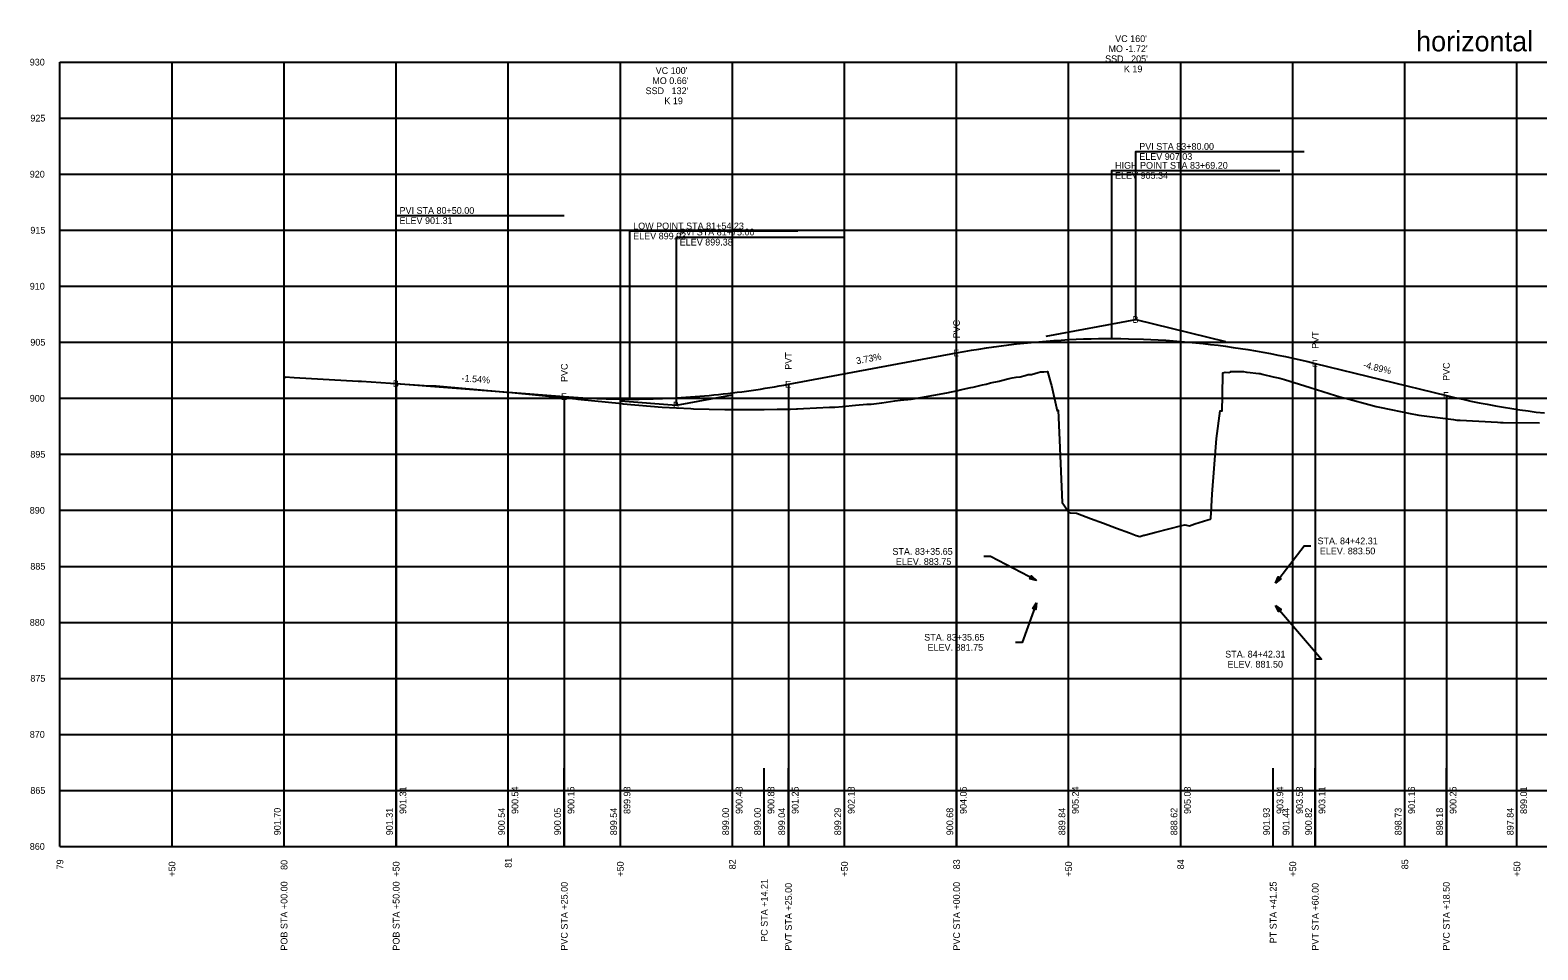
# Model space of a CAD drawing. Extents: x 76292 to 78417, y 50412 to 52585.
# Drawn here: x 76292 to 76965, y 52134 to 52544 of the extents above; entities that cross this region are included whole.
import ezdxf

# ---------------------------------------------------------------- set-up
doc = ezdxf.new("R2010")
doc.units = 0
for name, color, linetype in [('1', 7, 'Continuous'), ('2', 7, 'Continuous'), ('3', 7, 'Continuous'), ('32', 7, 'Continuous'), ('33', 7, 'Continuous'), ('63', 7, 'Continuous'), ('Default', 7, 'Continuous')]:
    doc.layers.add(name, color=color, linetype=linetype)

msp = doc.modelspace()

# ---------------------------------------------------------------- linework, layer by layer
at = {"layer": '1'}
for p, q in [((76305.34, 52180.05), (77605.34, 52180.05)), ((76305.34, 52180.05), (76305.34, 52180.05)), ((76355.34, 52180.05), (76355.34, 52180.05)), ((76405.34, 52180.05), (76405.34, 52180.05)), ((76455.34, 52180.05), (76455.34, 52180.05)), ((76505.34, 52180.05), (76505.34, 52180.05)), ((76555.34, 52180.05), (76555.34, 52180.05)), ((76605.34, 52180.05), (76605.34, 52180.05)), ((76655.34, 52180.05), (76655.34, 52180.05)), ((76705.34, 52180.05), (76705.34, 52180.05)), ((76755.34, 52180.05), (76755.34, 52180.05)), ((76805.34, 52180.05), (76805.34, 52180.05)), ((76855.34, 52180.05), (76855.34, 52180.05)), ((76905.34, 52180.05), (76905.34, 52180.05)), ((76955.34, 52180.05), (76955.34, 52180.05))]:
    msp.add_line(p, q, dxfattribs=at)
for points in [[(76785.34, 52415.2), (76785.34, 52490.2), (76860.34, 52490.2)], [(76774.54, 52406.73), (76774.54, 52481.73), (76849.54, 52481.73)], [(76455.34, 52386.6), (76455.34, 52461.6), (76530.34, 52461.6)], [(76559.57, 52379.7), (76559.57, 52454.7), (76634.57, 52454.7)], [(76580.34, 52376.97), (76580.34, 52451.97), (76655.34, 52451.97)], [(76705.34, 52400.28), (76705.34, 52180.05), (76705.34, 52180.05), (76705.34, 52180.05)], [(76865.34, 52395.62), (76865.34, 52180.05), (76865.34, 52180.05), (76865.34, 52180.05)], [(76455.34, 52386.6), (76455.34, 52180.05), (76455.34, 52180.05), (76455.34, 52180.05)], [(76630.34, 52386.29), (76630.34, 52180.05), (76630.34, 52180.05), (76630.34, 52180.05)], [(76530.34, 52380.82), (76530.34, 52180.05), (76530.34, 52180.05), (76530.34, 52180.05)], [(76923.84, 52381.31), (76923.84, 52180.05), (76923.84, 52180.05), (76923.84, 52180.05)], [(76305.34, 52180.05), (76305.34, 52215.05)], [(76305.34, 52180.05), (76305.34, 52215.05)], [(76305.34, 52180.05), (76305.34, 52215.05)], [(76305.34, 52180.05), (76305.34, 52215.05)], [(76355.34, 52180.05), (76355.34, 52215.05)], [(76355.34, 52180.05), (76355.34, 52215.05)], [(76355.34, 52180.05), (76355.34, 52215.05)], [(76355.34, 52180.05), (76355.34, 52215.05)], [(76405.34, 52180.05), (76405.34, 52215.05)], [(76405.34, 52180.05), (76405.34, 52215.05)], [(76405.34, 52180.05), (76405.34, 52215.05)], [(76405.34, 52180.05), (76405.34, 52215.05)], [(76455.34, 52180.05), (76455.34, 52215.05)], [(76455.34, 52180.05), (76455.34, 52215.05)], [(76455.34, 52180.05), (76455.34, 52215.05)], [(76455.34, 52180.05), (76455.34, 52215.05)], [(76505.34, 52180.05), (76505.34, 52215.05)], [(76505.34, 52180.05), (76505.34, 52215.05)], [(76505.34, 52180.05), (76505.34, 52215.05)], [(76505.34, 52180.05), (76505.34, 52215.05)], [(76530.34, 52180.05), (76530.34, 52215.05)], [(76530.34, 52180.05), (76530.34, 52215.05)], [(76530.34, 52180.05), (76530.34, 52215.05)], [(76530.34, 52180.05), (76530.34, 52215.05)], [(76555.34, 52180.05), (76555.34, 52215.05)], [(76555.34, 52180.05), (76555.34, 52215.05)], [(76555.34, 52180.05), (76555.34, 52215.05)], [(76555.34, 52180.05), (76555.34, 52215.05)], [(76605.34, 52180.05), (76605.34, 52215.05)], [(76605.34, 52180.05), (76605.34, 52215.05)], [(76605.34, 52180.05), (76605.34, 52215.05)], [(76605.34, 52180.05), (76605.34, 52215.05)], [(76619.55, 52180.05), (76619.55, 52215.05)], [(76619.55, 52180.05), (76619.55, 52215.05)], [(76619.55, 52180.05), (76619.55, 52215.05)], [(76619.55, 52180.05), (76619.55, 52215.05)], [(76630.34, 52180.05), (76630.34, 52215.05)], [(76630.34, 52180.05), (76630.34, 52215.05)], [(76630.34, 52180.05), (76630.34, 52215.05)], [(76630.34, 52180.05), (76630.34, 52215.05)], [(76655.34, 52180.05), (76655.34, 52215.05)], [(76655.34, 52180.05), (76655.34, 52215.05)], [(76655.34, 52180.05), (76655.34, 52215.05)], [(76655.34, 52180.05), (76655.34, 52215.05)], [(76705.34, 52180.05), (76705.34, 52215.05)], [(76705.34, 52180.05), (76705.34, 52215.05)], [(76705.34, 52180.05), (76705.34, 52215.05)], [(76705.34, 52180.05), (76705.34, 52215.05)], [(76755.34, 52180.05), (76755.34, 52215.05)], [(76755.34, 52180.05), (76755.34, 52215.05)], [(76755.34, 52180.05), (76755.34, 52215.05)], [(76755.34, 52180.05), (76755.34, 52215.05)], [(76805.34, 52180.05), (76805.34, 52215.05)], [(76805.34, 52180.05), (76805.34, 52215.05)], [(76805.34, 52180.05), (76805.34, 52215.05)], [(76805.34, 52180.05), (76805.34, 52215.05)], [(76846.59, 52180.05), (76846.59, 52215.05)], [(76846.59, 52180.05), (76846.59, 52215.05)], [(76846.59, 52180.05), (76846.59, 52215.05)], [(76846.59, 52180.05), (76846.59, 52215.05)], [(76855.34, 52180.05), (76855.34, 52215.05)], [(76855.34, 52180.05), (76855.34, 52215.05)], [(76855.34, 52180.05), (76855.34, 52215.05)], [(76855.34, 52180.05), (76855.34, 52215.05)], [(76865.34, 52180.05), (76865.34, 52215.05)], [(76865.34, 52180.05), (76865.34, 52215.05)], [(76865.34, 52180.05), (76865.34, 52215.05)], [(76865.34, 52180.05), (76865.34, 52215.05)], [(76905.34, 52180.05), (76905.34, 52215.05)], [(76905.34, 52180.05), (76905.34, 52215.05)], [(76905.34, 52180.05), (76905.34, 52215.05)], [(76905.34, 52180.05), (76905.34, 52215.05)], [(76923.84, 52180.05), (76923.84, 52215.05)], [(76923.84, 52180.05), (76923.84, 52215.05)], [(76923.84, 52180.05), (76923.84, 52215.05)], [(76923.84, 52180.05), (76923.84, 52215.05)], [(76955.34, 52180.05), (76955.34, 52215.05)], [(76955.34, 52180.05), (76955.34, 52215.05)], [(76955.34, 52180.05), (76955.34, 52215.05)], [(76955.34, 52180.05), (76955.34, 52215.05)]]:
    msp.add_lwpolyline(points, dxfattribs=at)
at = {"layer": '2'}
msp.add_lwpolyline([(76405.34, 52388.53), (76405.72, 52389.55), (76405.74, 52389.55), (76405.77, 52389.55), (76405.8, 52389.55), (76405.83, 52389.55), (76405.84, 52389.55), (76409.89, 52389.33), (76438.41, 52387.74), (76438.7, 52387.72), (76439, 52387.7), (76439.5, 52387.68), (76439.8, 52387.66), (76469.99, 52385.61), (76470.25, 52385.62), (76473.18, 52385.54), (76504.5, 52382.84), (76504.62, 52382.82), (76504.68, 52382.82), (76505.52, 52382.73), (76535.43, 52379.78), (76536.4, 52379.67), (76556.09, 52377.67), (76556.59, 52377.63), (76573.97, 52376.13), (76574.05, 52376.12), (76586.85, 52375.44), (76587.97, 52375.38), (76601.91, 52375.05), (76601.93, 52375.05), (76617.76, 52375), (76617.89, 52374.99), (76619.55, 52375.03), (76625.37, 52375.15), (76631.19, 52375.26), (76633.97, 52375.31), (76634.41, 52375.31), (76637.01, 52375.45), (76642.83, 52375.74), (76648.65, 52376.03), (76649.9, 52376.09), (76650.97, 52376.12), (76654.48, 52376.42), (76660.3, 52376.93), (76665.3, 52377.36), (76666.12, 52377.41), (76667.28, 52377.48), (76671.94, 52378.09), (76677.76, 52378.85), (76680.3, 52379.18), (76683.39, 52379.47), (76683.58, 52379.49), (76685.13, 52379.7), (76689.41, 52380.47), (76695.23, 52381.5), (76697.73, 52381.93), (76700.08, 52382.33), (76701.05, 52382.54), (76705.95, 52383.57), (76706.87, 52383.78), (76711.67, 52384.85), (76712.69, 52385.07), (76716.91, 52385.99), (76718.51, 52386.4), (76720.49, 52386.91), (76724.33, 52387.72), (76724.76, 52387.81), (76728.73, 52388.85), (76730.16, 52389.11), (76731.98, 52389.44), (76733.71, 52389.66), (76735.98, 52390.26), (76737.29, 52390.6), (76738.76, 52390.72), (76741.8, 52391.52), (76742.83, 52391.8), (76744.21, 52391.87), (76745.72, 52391.94), (76745.88, 52391.97), (76745.95, 52392.04), (76747.4, 52386.71), (76747.62, 52385.73), (76750.15, 52374.5), (76750.66, 52374.67), (76751.33, 52361.35), (76752.43, 52333.53), (76753.44, 52332.03), (76754.96, 52329.77), (76755.47, 52329.08), (76755.96, 52328.88), (76758.86, 52328.73), (76759.26, 52328.58), (76765.09, 52326.43), (76770.91, 52324.28), (76776.73, 52322.13), (76782.55, 52319.98), (76785.49, 52318.89), (76787.04, 52318.44), (76788.37, 52318.8), (76788.82, 52318.93), (76789.23, 52318.95), (76794.19, 52320.24), (76800.01, 52321.75), (76805.84, 52323.27), (76807.15, 52323.61), (76809.26, 52323.18), (76811.66, 52323.95), (76817.48, 52325.8), (76818.55, 52326.14), (76818.76, 52326.41), (76819.35, 52337.31), (76821.23, 52362.08), (76822.95, 52374.5), (76823.3, 52374.47), (76823.34, 52374.47), (76823.76, 52374.46), (76823.92, 52381.17), (76824.16, 52391.42), (76825.22, 52391.66), (76826.82, 52391.6), (76827.47, 52391.92), (76827.55, 52392), (76829.12, 52391.99), (76833.33, 52391.93), (76834.69, 52391.71), (76834.94, 52391.68), (76840.2, 52391.17), (76840.77, 52391.05), (76841.64, 52390.87), (76846.59, 52389.69), (76849.53, 52388.99), (76851.7, 52388.37), (76860.68, 52385.6), (76863.14, 52384.83), (76874.45, 52381.33), (76877.4, 52380.47), (76878.88, 52380.07), (76890.96, 52376.78), (76892.46, 52376.41), (76894.06, 52376.04), (76908.38, 52373.08), (76910.03, 52372.75), (76911.57, 52372.51), (76926.98, 52370.52), (76928.51, 52370.35), (76930.01, 52370.26), (76946.68, 52369.33), (76948, 52369.31), (76949.25, 52369.31), (76965.37, 52369.09)], dxfattribs=at)
at = {"layer": '32'}
for p, q in [((76630.34, 52386.29), (76705.34, 52400.28)), ((76865.34, 52395.62), (76923.84, 52381.31)), ((76455.34, 52386.6), (76530.34, 52380.82))]:
    msp.add_line(p, q, dxfattribs=at)
for points in [[(76745.34, 52407.74), (76785.34, 52415.2), (76825.34, 52405.41)], [(76705.34, 52400.28), (76708.67, 52400.89), (76712.01, 52401.46), (76715.34, 52402.01), (76718.67, 52402.53), (76722.01, 52403.01), (76725.34, 52403.47), (76728.67, 52403.9), (76732.01, 52404.29), (76735.34, 52404.66), (76738.67, 52405), (76742.01, 52405.3), (76745.34, 52405.58), (76748.67, 52405.83), (76752.01, 52406.05), (76755.34, 52406.23), (76758.67, 52406.39), (76762.01, 52406.52), (76765.34, 52406.62), (76768.67, 52406.68), (76772.01, 52406.72), (76775.34, 52406.73), (76778.67, 52406.71), (76782.01, 52406.65), (76788.67, 52406.46), (76792.01, 52406.32), (76795.34, 52406.15), (76798.67, 52405.95), (76802.01, 52405.71), (76805.34, 52405.45), (76808.67, 52405.16), (76812.01, 52404.84), (76815.34, 52404.49), (76818.67, 52404.11), (76822.01, 52403.69), (76825.34, 52403.25), (76828.67, 52402.78), (76832.01, 52402.28), (76835.34, 52401.75), (76838.67, 52401.19), (76842.01, 52400.6), (76845.34, 52399.98), (76848.67, 52399.32), (76852.01, 52398.64), (76855.34, 52397.93), (76858.67, 52397.19), (76862.01, 52396.42), (76865.34, 52395.62)], [(76530.34, 52380.82), (76532.42, 52380.67), (76534.51, 52380.52), (76536.59, 52380.39), (76538.67, 52380.27), (76540.76, 52380.16), (76542.84, 52380.06), (76544.92, 52379.98), (76547.01, 52379.9), (76549.09, 52379.84), (76551.17, 52379.79), (76553.26, 52379.75), (76555.34, 52379.72), (76557.42, 52379.7), (76559.51, 52379.7), (76561.59, 52379.7), (76563.67, 52379.72), (76565.76, 52379.75), (76567.84, 52379.79), (76569.92, 52379.84), (76572.01, 52379.9), (76574.09, 52379.97), (76576.17, 52380.06), (76578.26, 52380.16), (76582.42, 52380.38), (76584.51, 52380.52), (76586.59, 52380.66), (76588.67, 52380.81), (76590.76, 52380.98), (76592.84, 52381.15), (76594.92, 52381.34), (76597.01, 52381.54), (76599.09, 52381.75), (76601.17, 52381.98), (76603.26, 52382.21), (76605.34, 52382.46), (76607.42, 52382.71), (76609.51, 52382.98), (76611.59, 52383.26), (76613.67, 52383.55), (76615.76, 52383.85), (76617.84, 52384.17), (76619.92, 52384.49), (76622.01, 52384.83), (76624.09, 52385.18), (76626.17, 52385.54), (76628.26, 52385.91), (76630.34, 52386.29)], [(76555.34, 52378.9), (76580.34, 52376.97), (76605.34, 52381.63)], [(76923.84, 52381.31), (76927.49, 52380.43), (76931.13, 52379.6), (76934.78, 52378.81), (76938.42, 52378.06), (76942.07, 52377.35), (76945.71, 52376.68), (76949.36, 52376.04), (76953.01, 52375.45), (76956.65, 52374.9), (76960.3, 52374.39), (76963.94, 52373.92), (76967.59, 52373.49)]]:
    msp.add_lwpolyline(points, dxfattribs=at)
at = {"layer": '63'}
for p, q in [((76305.34, 52180.05), (76305.34, 52530.05)), ((76305.34, 52530.05), (76305.34, 52530.05)), ((76305.34, 52530.05), (76305.34, 52530.05)), ((76305.34, 52530.05), (77605.34, 52530.05)), ((76305.34, 52530.05), (77605.34, 52530.05)), ((76355.34, 52180.05), (76355.34, 52530.05)), ((76405.34, 52180.05), (76405.34, 52530.05)), ((76455.34, 52180.05), (76455.34, 52530.05)), ((76505.34, 52180.05), (76505.34, 52530.05)), ((76555.34, 52180.05), (76555.34, 52530.05)), ((76605.34, 52180.05), (76605.34, 52530.05)), ((76655.34, 52180.05), (76655.34, 52530.05)), ((76705.34, 52180.05), (76705.34, 52530.05)), ((76755.34, 52180.05), (76755.34, 52530.05)), ((76805.34, 52180.05), (76805.34, 52530.05)), ((76855.34, 52180.05), (76855.34, 52530.05)), ((76905.34, 52180.05), (76905.34, 52530.05)), ((76955.34, 52180.05), (76955.34, 52530.05)), ((76305.34, 52505.05), (76305.34, 52505.05)), ((76305.34, 52505.05), (77605.34, 52505.05)), ((76305.34, 52480.05), (76305.34, 52480.05)), ((76305.34, 52480.05), (77605.34, 52480.05)), ((76305.34, 52455.05), (76305.34, 52455.05)), ((76305.34, 52455.05), (77605.34, 52455.05)), ((76305.34, 52430.05), (76305.34, 52430.05)), ((76305.34, 52430.05), (77605.34, 52430.05)), ((76305.34, 52405.05), (76305.34, 52405.05)), ((76305.34, 52405.05), (77605.34, 52405.05)), ((76305.34, 52380.05), (76305.34, 52380.05)), ((76305.34, 52380.05), (77605.34, 52380.05)), ((76305.34, 52355.05), (76305.34, 52355.05)), ((76305.34, 52355.05), (77605.34, 52355.05)), ((76305.34, 52330.05), (76305.34, 52330.05)), ((76305.34, 52330.05), (77605.34, 52330.05)), ((76305.34, 52305.05), (76305.34, 52305.05)), ((76305.34, 52305.05), (77605.34, 52305.05)), ((76305.34, 52280.05), (76305.34, 52280.05)), ((76305.34, 52280.05), (77605.34, 52280.05)), ((76305.34, 52255.05), (76305.34, 52255.05)), ((76305.34, 52255.05), (77605.34, 52255.05)), ((76305.34, 52230.05), (76305.34, 52230.05)), ((76305.34, 52230.05), (77605.34, 52230.05)), ((76305.34, 52205.05), (76305.34, 52205.05)), ((76305.34, 52205.05), (77605.34, 52205.05)), ((76305.34, 52180.05), (76305.34, 52180.05))]:
    msp.add_line(p, q, dxfattribs=at)
at = {"layer": 'Default'}
for points in [[(76740.99, 52298.8), (76720.44, 52309.44), (76717.44, 52309.44)], [(76847.65, 52297.55), (76860.36, 52314.15), (76863.36, 52314.15)], [(76740.99, 52288.8), (76734.61, 52271.14), (76731.61, 52271.14)], [(76847.65, 52287.55), (76868.19, 52263.61), (76865.19, 52263.61)]]:
    msp.add_lwpolyline(points, dxfattribs=at)
for points in [[(76740.99, 52298.8), (76738.07, 52299.49), (76738.74, 52300.78)], [(76847.65, 52297.55), (76848.84, 52300.3), (76850, 52299.41)], [(76740.99, 52288.8), (76740.68, 52285.81), (76739.32, 52286.31)], [(76847.65, 52287.55), (76850.1, 52285.81), (76848.99, 52284.86)]]:
    msp.add_lwpolyline(points, close=True, dxfattribs=at)

# ---------------------------------------------------------------- texts
at = {"layer": '1'}
for s, height, p in [('horizontal', 9, (76910.34, 52534.85)), ('STA. 84+42.31', 3, (76866.36, 52314.9)), ('STA. 83+35.65', 3, (76676.73, 52310.19)), ('ELEV. 883.75', 3, (76678.23, 52305.69)), ('ELEV. 883.50', 3, (76867.39, 52310.4)), ('STA. 83+35.65', 3, (76690.91, 52271.89)), ('ELEV. 881.75', 3, (76692.41, 52267.39)), ('STA. 84+42.31', 3, (76825.18, 52264.36)), ('ELEV. 881.50', 3, (76826.2, 52259.86))]:
    msp.add_text(s, height=height, dxfattribs=at).set_placement(p)
for s, p in [('79', (76306.84, 52169.82)), ('80', (76406.84, 52169.59)), ('81', (76506.84, 52170.53)), ('82', (76606.84, 52169.85)), ('83', (76706.84, 52169.85)), ('84', (76806.84, 52169.85)), ('85', (76906.84, 52169.85)), ('+50', (76356.84, 52166.59)), ('+50', (76456.84, 52166.59)), ('+50', (76556.84, 52166.59)), ('+50', (76656.84, 52166.59)), ('+50', (76756.84, 52166.59)), ('+50', (76856.84, 52166.59)), ('+50', (76956.84, 52166.59))]:
    msp.add_text(s, height=3, rotation=90, dxfattribs=at).set_placement(p)
at = {"layer": '3'}
for s, p in [('901.70', (76403.84, 52185.05)), ('901.31', (76453.84, 52185.05)), ('900.54', (76503.84, 52185.05)), ('900.05', (76528.84, 52185.05)), ('899.54', (76553.84, 52185.05)), ('899.00', (76603.84, 52185.05)), ('899.00', (76618.05, 52185.05)), ('899.04', (76628.84, 52185.05)), ('899.29', (76653.84, 52185.05)), ('900.68', (76703.84, 52185.05)), ('889.84', (76753.84, 52185.05)), ('888.62', (76803.84, 52185.05)), ('901.93', (76845.09, 52185.05)), ('901.44', (76853.84, 52185.05)), ('900.82', (76863.84, 52185.05)), ('898.73', (76903.84, 52185.05)), ('898.18', (76922.34, 52185.05)), ('897.84', (76953.84, 52185.05))]:
    msp.add_text(s, height=3, rotation=90, dxfattribs=at).set_placement(p)
at = {"layer": '33'}
for s, p in [("MO -1.72'", (76773.1, 52534.53)), ("VC 160'", (76776.1, 52539.03)), ("SSD   205'", (76771.6, 52530.03)), ("VC 100'", (76571.1, 52524.77)), ('K 19', (76779.98, 52525.53)), ("SSD   132'", (76566.6, 52515.77)), ("MO 0.66'", (76569.6, 52520.27)), ('K 19', (76574.98, 52511.27)), ('B', (76783.84, 52413.7)), ('B', (76453.84, 52385.1)), ('B', (76578.84, 52375.47))]:
    msp.add_text(s, height=3, dxfattribs=at).set_placement(p)
for s, rotation, p in [('PVI STA 83+80.00', 360, (76786.84, 52490.95)), ('HIGH POINT STA 83+69.20', 360, (76776.04, 52482.48)), ('ELEV 907.03', 360, (76786.84, 52486.45)), ('ELEV 905.34', 360, (76776.04, 52477.98)), ('PVI STA 80+50.00', 360, (76456.84, 52462.35)), ('ELEV 901.31', 360, (76456.84, 52457.85)), ('LOW POINT STA 81+54.23', 360, (76561.07, 52455.45)), ('ELEV 899.93', 360, (76561.07, 52450.95)), ('PVI STA 81+75.00', 360, (76581.84, 52452.72)), ('ELEV 899.38', 360, (76581.84, 52448.22)), ('PVC', 90, (76706.84, 52406.78)), ('PVT', 90, (76866.84, 52402.12)), ('PVT', 90, (76631.84, 52392.79)), ('3.73%', 10.56227, (76660.82, 52395.24)), ('E', 360, (76703.84, 52398.78)), ('E', 360, (76863.84, 52394.12)), ('-4.89%', 346.25044, (76886.51, 52393.71)), ('PVC', 90, (76925.34, 52387.81)), ('-1.54%', 355.59691, (76484.42, 52387.61)), ('PVC', 90, (76531.84, 52387.32)), ('E', 360, (76528.84, 52379.32)), ('E', 360, (76628.84, 52384.79)), ('E', 360, (76922.34, 52379.81)), ('901.31', 90, (76459.84, 52194.55)), ('900.54', 90, (76509.84, 52194.55)), ('900.15', 90, (76534.84, 52194.55)), ('899.93', 90, (76559.84, 52194.55)), ('900.48', 90, (76609.84, 52194.55)), ('900.88', 90, (76624.05, 52194.55)), ('901.25', 90, (76634.84, 52194.55)), ('902.18', 90, (76659.84, 52194.55)), ('904.05', 90, (76709.84, 52194.55)), ('905.24', 90, (76759.84, 52194.55)), ('905.08', 90, (76809.84, 52194.55)), ('903.94', 90, (76851.09, 52194.55)), ('903.58', 90, (76859.84, 52194.55)), ('903.11', 90, (76869.84, 52194.55)), ('901.16', 90, (76909.84, 52194.55)), ('900.25', 90, (76928.34, 52194.55)), ('899.01', 90, (76959.84, 52194.55)), ('POB STA +00.00', 90, (76406.84, 52133.59)), ('POB STA +50.00', 90, (76456.84, 52133.59)), ('PVC STA +25.00', 90, (76531.84, 52133.59)), ('PC STA +14.21', 90, (76621.05, 52137.53)), ('PVT STA +25.00', 90, (76631.84, 52133.59)), ('PVC STA +00.00', 90, (76706.84, 52133.59)), ('PT STA +41.25', 90, (76848.09, 52136.85)), ('PVT STA +60.00', 90, (76866.84, 52133.59)), ('PVC STA +18.50', 90, (76925.34, 52133.59))]:
    msp.add_text(s, height=3, rotation=rotation, dxfattribs=at).set_placement(p)
at = {"layer": '63'}
for s, height, p in [('930', 3, (76291.88, 52528.55)), ('930', 3, (76291.88, 52528.55)), ('925', 3, (76292.14, 52503.55)), ('920', 3, (76291.88, 52478.55)), ('915', 3, (76292.14, 52453.55)), ('910', 3, (76291.88, 52428.55)), ('905', 3, (76292.14, 52403.55)), ('900', 3, (76291.88, 52378.55)), ('895', 3, (76292.14, 52353.55)), ('890', 3, (76291.88, 52328.55)), ('885', 3, (76292.14, 52303.55)), ('880', 3, (76291.88, 52278.55)), ('875', 3, (76292.14, 52253.55)), ('870', 3, (76291.88, 52228.55)), ('865', 3, (76292.14, 52203.55)), ('860', 3, (76291.88, 52178.55)), ('-', 0.0025, (76305.34, 52180.04))]:
    msp.add_text(s, height=height, dxfattribs=at).set_placement(p)

doc.saveas('drawing.dxf')
